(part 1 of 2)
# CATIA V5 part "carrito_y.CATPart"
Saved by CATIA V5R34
Part number: Part4
Bounding box of the stored display mesh (mm): x -115.5 to 115.5, y -20 to 5, z -75 to 75
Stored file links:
  C:\Users\Apolinar\Desktop\cnc\carrito_y.CATPart
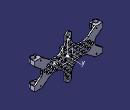
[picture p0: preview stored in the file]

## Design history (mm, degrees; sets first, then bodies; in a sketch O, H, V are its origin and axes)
AxisSystem1: origin (0, 0, 0), X (1, 0, 0), Y (0, 1, 0), Z (0, 0, 1)
Body1 (main body)
  Sketch1 on ZX plane of AxisSystem1, origin (0, 0, 0), H (0, 0, 1), V (1, 0, 0)
    point P1 (-20, 58.9576)
    point P2 (-45, 116.5)
    line L1 (-45, 116.5) -> (-30, 116.5)
    point P3 (-30, 116.5)
    line L2 (-30, 116.5) -> (-9.642, 90)
    point P4 (-9.642, 90)
    line L3 (-9.642, 90) -> (0, 90)
    point P5 (0, 90)
    line L4 (-20, 58.9576) -> (-20, 31.2132)
    point P6 (-20, 0)
    point P7 (0, 90)
    point P8 (-20, 0)
    line L5 (-45, 116.5) -> (-45, 91.5)
    point P9 (-45, 91.5)
    line L6 (-45, 91.5) -> (-20, 58.9576)
    point P10 (20, 58.9576)
    point P11 (45, 116.5)
    point P12 (30, 116.5)
    point P13 (9.642, 90)
    point P14 (20, 0)
    point P15 (45, 91.5)
    line L7 (45, 116.5) -> (30, 116.5)
    line L8 (30, 116.5) -> (9.642, 90)
    line L9 (20, 58.9576) -> (20, 31.2132)
    line L10 (45, 116.5) -> (45, 91.5)
    line L11 (45, 91.5) -> (20, 58.9576)
    point P16 (0, 90)
    line L12 (9.642, 90) -> (0, 90)
    point P17 (-45, -116.5)
    point P18 (-30, -116.5)
    point P19 (-9.642, -90)
    point P20 (0, -90)
    point P21 (0, -90)
    point P22 (-45, -91.5)
    point P23 (45, -116.5)
    point P24 (30, -116.5)
    point P25 (9.642, -90)
    point P26 (45, -91.5)
    point P27 (0, -90)
    line L13 (-45, -116.5) -> (-30, -116.5)
    line L14 (-30, -116.5) -> (-9.642, -90)
    line L15 (-9.642, -90) -> (0, -90)
    line L16 (-45, -116.5) -> (-45, -91.5)
    line L17 (45, -116.5) -> (30, -116.5)
    line L18 (30, -116.5) -> (9.642, -90)
    line L19 (45, -116.5) -> (45, -91.5)
    line L20 (9.642, -90) -> (0, -90)
    point P28 (20, -58.9576)
    line L21 (45, -91.5) -> (20, -58.9576)
    point P29 (20, 0)
    line L22 (20, -58.9576) -> (20, -31.2132)
    point P30 (-20, -58.9576)
    point P31 (-20, 0)
    line L23 (-20, -58.9576) -> (-20, -31.2132)
    line L24 (-45, -91.5) -> (-20, -58.9576)
    construction line L25 (-45, 104) -> (-65.3473, 104)
    point P32 (-45, 104)
    axis line L26 (-45, -104) -> (-57.4598, -104)
    point P34 (-45, -104)
    point P36 (-20, 10)
    line L27 (-41.2132, 10) -> (-69.2265, 10)
    point P37 (-69.2265, 10)
    line L28 (-69.2265, 10) -> (-75, 0)
    point P38 (-75, 0)
    point P39 (-75, 0)
    point P40 (-69.2265, -10)
    line L29 (-69.2265, -10) -> (-75, 0)
    point P41 (-20, -10)
    line L30 (-41.2132, -10) -> (-69.2265, -10)
    point P42 (69.2265, 10)
    point P43 (75, 0)
    point P44 (75, 0)
    point P45 (69.2265, -10)
    line L31 (69.2265, 10) -> (75, 0)
    line L32 (69.2265, -10) -> (75, 0)
    point P46 (20, 10)
    line L33 (41.2132, 10) -> (69.2265, 10)
    point P47 (20, -10)
    line L34 (41.2132, -10) -> (69.2265, -10)
    line L35 (-41.2132, 10) -> (-20, 31.2132)
    line L36 (41.2132, 10) -> (20, 31.2132)
    line L37 (41.2132, -10) -> (20, -31.2132)
    line L38 (-41.2132, -10) -> (-20, -31.2132)
    length L1 = 15
    length L5 = 25
    distance L25 L26 = 208
    distance P3 P12 = 60
    distance L4 V = 20
    distance L3 H = 90
    length L6 = 41.0367
    distance P38 L4 = 55
    distance L30 L27 = 20
    angle L27 L35 = 45
    length L35 = 30
    angle L33 L36 = 45
    length L36 = 30
    angle L34 L37 = 45
    length L37 = 30
    angle L30 L38 = 45
    length L38 = 30
    angle L29 L30 = 120
    horizontal: L1 H, L3 H, L25 H, L26 H, L27 H
    coincidence: P5 V, P6 H, P5 P7, P6 P8, P4 L12, P38 H, L27 P36, L4 P36, L33 P46, L9 P46, L34 P47, L22 P47, L30 P41, L23 P41
    vertical: L4 V, L5 V
    parallelism: L6 L2
    symmetry: P1 P10 V, P2 P11 V, P3 P12 V, P4 P13 V, P8 P14 V, P9 P15 V, L1 L7 V, L2 L8 V, L4 L9 V, L5 L10 V, L6 L11 V, P5 P16 V, L3 L12 V, P2 P17 H, P3 P18 H, P4 P19 H, P5 P20 H, P7 P21 H, P9 P22 H, P11 P23 H, P12 P24 H, P13 P25 H, P15 P26 H, P16 P27 H, L1 L13 H, L2 L14 H, L3 L15 H, L5 L16 H, L7 L17 H, L8 L18 H, L10 L19 H, L12 L20 H, P10 P28 H, L11 L21 H, P14 P29 H, L9 L22 H, P1 P30 H, P8 P31 H, L4 L23 H, L6 L24 H, P38 P39 H, P37 P40 H, L28 L29 H, P36 P41 H, L27 L30 H, P37 P42 V, P38 P43 V, P39 P44 V, P40 P45 V, L28 L31 V, L29 L32 V, P36 P46 V, L27 L33 V, P41 P47 V, L30 L34 V
    midpoint: P34 L16, L5 P32
  Pad1: profile Sketch1, direction (0, 1, 0), length 5
  Sketch2 on start face of Pad1, origin (0, 0, 0), H (1, 0, 0), V (0, 0, 1)
    point P1 (-116.5, 45)
    line L1 (-116.5, 45) -> (-91.5, 45)
    line L2 (-91.5, 45) -> (-91.5, 30)
    line L3 (-91.5, 30) -> (-116.5, 30)
    line L4 (-116.5, 30) -> (-116.5, 45)
    point P2 (-91.5, 45)
    point P3 (-91.5, 30)
    point P4 (-116.5, 30)
    reference projected line E1 (-116.5, 30) -> (-116.5, 45) from edge [start face of Pad1 | face of Pad1 from Sketch1.L17]
    reference projected point E2 (-116.5, 30) from vertex [start face of Pad1 | face of Pad1 from Sketch1.L18 | face of Pad1 from Sketch1.L17]
    point P5 (116.5, 45)
    point P6 (91.5, 45)
    point P7 (91.5, 30)
    point P8 (116.5, 30)
    line L5 (116.5, 45) -> (91.5, 45)
    line L6 (91.5, 45) -> (91.5, 30)
    line L7 (91.5, 30) -> (116.5, 30)
    line L8 (116.5, 30) -> (116.5, 45)
    point P9 (-116.5, -45)
    point P10 (-91.5, -45)
    point P11 (-91.5, -30)
    point P12 (-116.5, -30)
    point P13 (116.5, -45)
    point P14 (91.5, -45)
    point P15 (91.5, -30)
    point P16 (116.5, -30)
    line L9 (-116.5, -45) -> (-91.5, -45)
    line L10 (-91.5, -45) -> (-91.5, -30)
    line L11 (-91.5, -30) -> (-116.5, -30)
    line L12 (-116.5, -30) -> (-116.5, -45)
    line L13 (116.5, -45) -> (91.5, -45)
    line L14 (91.5, -45) -> (91.5, -30)
    line L15 (91.5, -30) -> (116.5, -30)
    line L16 (116.5, -30) -> (116.5, -45)
    reference projected point E3 (-91.5, 45) from vertex [start face of Pad1 | face of Pad1 from Sketch1.L19 | face of Pad1 from Sketch1.L21]
    length L4 = 15
    horizontal: L1 H, L3 H
    vertical: L2 V, L4 V
    coincidence: E1 L4, E2 L3, L2 E3
    symmetry: P1 P5 V, P2 P6 V, P3 P7 V, P4 P8 V, L1 L5 V, L2 L6 V, L3 L7 V, L4 L8 V, P1 P9 H, P2 P10 H, P3 P11 H, P4 P12 H, P5 P13 H, P6 P14 H, P7 P15 H, P8 P16 H, L1 L9 H, L2 L10 H, L3 L11 H, L4 L12 H, L5 L13 H, L6 L14 H, L7 L15 H, L8 L16 H
  Pad2: profile Sketch2, direction (0, -1, 0), length 20
  Sketch3 on face of Pad2, origin (0, 0, -45), H (1, 0, 0), V (0, -1, 0)
    arc A1 centre (-107, 10) radius 7.5 from (-99.567, 11) to (-99.567, 9) ccw
    point P1 (-107, 10)
    point P2 (-99.567, 11)
    line L1 (-99.567, 11) -> (-91.5, 11)
    point P3 (-91.5, 11)
    line L2 (-91.5, 11) -> (-91.5, 9)
    point P4 (-91.5, 9)
    line L3 (-91.5, 9) -> (-99.567, 9)
    point P5 (-99.567, 9)
    reference projected line E1 (-116.5, 0) -> (-116.5, -5) from edge [face of Pad2 | face of Pad2]
    reference projected line E2 (-58.9576, 0) -> (-91.5, 0) from edge [start face of Pad1 | face of Pad1 from Sketch1.L24]
    reference projected line E3 (-91.5, 0) -> (-91.5, 20) from edge [face of Pad2 from Sketch2.L10 | face of Pad2]
    point P7 (99.567, 11)
    point P8 (91.5, 11)
    point P9 (91.5, 9)
    point P10 (99.567, 9)
    arc A2 centre (107, 10) radius 7.5 from (99.567, 11) to (99.567, 9) cw
    line L4 (99.567, 11) -> (91.5, 11)
    line L5 (91.5, 11) -> (91.5, 9)
    line L6 (91.5, 9) -> (99.567, 9)
    radius A1 = 7.5
    length L2 = 2
    distance E1 A1 = 2
    distance E2 P1 = 10
    distance P3 P1 V = 1
    horizontal: L1 H, L3 H
    vertical: L2 V
    coincidence: L2 E3
    symmetry: P2 P7 V, P3 P8 V, P4 P9 V, P5 P10 V, A1 A2 V, L1 L4 V, L2 L5 V, L3 L6 V
  Pocket1: profile Sketch3, direction (0, 0, 1), through (limit type 3)
  Sketch4 on start face of Pad1, origin (0, 0, 0), H (1, 0, 0), V (0, 0, 1)
    point P1 (0, 5)
    construction circle A1 centre (0, 0) radius 5.7735
    construction circle A2 centre (0, 0) radius 5
    point P2 (2.8868, 5)
    point P3 (-2.8868, 5)
    point P4 (-5.7735, 0)
    point P5 (-2.8868, -5)
    point P6 (2.8868, -5)
    point P7 (5.7735, 0)
    line L1 (2.8868, 5) -> (-2.8868, 5)
    line L2 (-2.8868, 5) -> (-5.7735, 0)
    line L3 (-5.7735, 0) -> (-2.8868, -5)
    line L4 (-2.8868, -5) -> (2.8868, -5)
    line L5 (2.8868, -5) -> (5.7735, 0)
    line L6 (5.7735, 0) -> (2.8868, 5)
    construction line L7 (0, 0) -> (0, 5)
    point P8 (-20, 5)
    point P9 (-17.1132, 5)
    point P10 (-22.8868, 5)
    line L8 (-17.1132, 5) -> (-22.8868, 5)
    point P11 (-17.1132, -5)
    point P12 (-22.8868, -5)
    line L9 (-22.8868, -5) -> (-17.1132, -5)
    point P13 (-14.2265, 0)
    line L10 (-17.1132, -5) -> (-14.2265, 0)
    line L11 (-14.2265, 0) -> (-17.1132, 5)
    point P14 (-25.7735, 0)
    line L12 (-22.8868, 5) -> (-25.7735, 0)
    line L13 (-25.7735, 0) -> (-22.8868, -5)
    point P15 (-40, 5)
    point P16 (-37.1132, 5)
    point P17 (-42.8868, 5)
    line L14 (-37.1132, 5) -> (-42.8868, 5)
    point P18 (-37.1132, -5)
    point P19 (-42.8868, -5)
    line L15 (-42.8868, -5) -> (-37.1132, -5)
    point P20 (-34.2265, 0)
    line L16 (-37.1132, -5) -> (-34.2265, 0)
    line L17 (-34.2265, 0) -> (-37.1132, 5)
    point P21 (-45.7735, 0)
    line L18 (-42.8868, 5) -> (-45.7735, 0)
    line L19 (-45.7735, 0) -> (-42.8868, -5)
    point P22 (-60, 5)
    point P23 (-57.1132, 5)
    point P24 (-62.8868, 5)
    line L20 (-57.1132, 5) -> (-62.8868, 5)
    point P25 (-57.1132, -5)
    point P26 (-62.8868, -5)
    line L21 (-62.8868, -5) -> (-57.1132, -5)
    point P27 (-54.2265, 0)
    line L22 (-57.1132, -5) -> (-54.2265, 0)
    line L23 (-54.2265, 0) -> (-57.1132, 5)
    point P28 (-65.7735, 0)
    line L24 (-62.8868, 5) -> (-65.7735, 0)
    line L25 (-65.7735, 0) -> (-62.8868, -5)
    point P29 (-80, 5)
    point P30 (-77.1132, 5)
    point P31 (-82.8868, 5)
    line L26 (-77.1132, 5) -> (-82.8868, 5)
    point P32 (-77.1132, -5)
    point P33 (-82.8868, -5)
    line L27 (-82.8868, -5) -> (-77.1132, -5)
    point P34 (-74.2265, 0)
    line L28 (-77.1132, -5) -> (-74.2265, 0)
    line L29 (-74.2265, 0) -> (-77.1132, 5)
    point P35 (-85.7735, 0)
    line L30 (-82.8868, 5) -> (-85.7735, 0)
    line L31 (-85.7735, 0) -> (-82.8868, -5)
    point P36 (20, 5)
    point P37 (17.1132, 5)
    point P38 (22.8868, 5)
    point P39 (17.1132, -5)
    point P40 (22.8868, -5)
    point P41 (14.2265, 0)
    point P42 (25.7735, 0)
    point P43 (40, 5)
    point P44 (37.1132, 5)
    point P45 (42.8868, 5)
    point P46 (37.1132, -5)
    point P47 (42.8868, -5)
    point P48 (34.2265, 0)
    point P49 (45.7735, 0)
    point P50 (60, 5)
    point P51 (57.1132, 5)
    point P52 (62.8868, 5)
    point P53 (57.1132, -5)
    point P54 (62.8868, -5)
    point P55 (54.2265, 0)
    point P56 (65.7735, 0)
    point P57 (80, 5)
    point P58 (77.1132, 5)
    point P59 (82.8868, 5)
    point P60 (77.1132, -5)
    point P61 (82.8868, -5)
    point P62 (74.2265, 0)
    point P63 (85.7735, 0)
    line L32 (17.1132, 5) -> (22.8868, 5)
    line L33 (22.8868, -5) -> (17.1132, -5)
    line L34 (17.1132, -5) -> (14.2265, 0)
    line L35 (14.2265, 0) -> (17.1132, 5)
    line L36 (22.8868, 5) -> (25.7735, 0)
    line L37 (25.7735, 0) -> (22.8868, -5)
    line L38 (37.1132, 5) -> (42.8868, 5)
    line L39 (42.8868, -5) -> (37.1132, -5)
    line L40 (37.1132, -5) -> (34.2265, 0)
    line L41 (34.2265, 0) -> (37.1132, 5)
    line L42 (42.8868, 5) -> (45.7735, 0)
    line L43 (45.7735, 0) -> (42.8868, -5)
    line L44 (57.1132, 5) -> (62.8868, 5)
    line L45 (62.8868, -5) -> (57.1132, -5)
    line L46 (57.1132, -5) -> (54.2265, 0)
    line L47 (54.2265, 0) -> (57.1132, 5)
    line L48 (62.8868, 5) -> (65.7735, 0)
    line L49 (65.7735, 0) -> (62.8868, -5)
    line L50 (77.1132, 5) -> (82.8868, 5)
    line L51 (82.8868, -5) -> (77.1132, -5)
    line L52 (77.1132, -5) -> (74.2265, 0)
    line L53 (74.2265, 0) -> (77.1132, 5)
    line L54 (82.8868, 5) -> (85.7735, 0)
    line L55 (85.7735, 0) -> (82.8868, -5)
    point P64 (9.9998, 10)
    point P65 (9.9998, 15)
    construction circle A3 centre (9.9998, 10) radius 5.7735
    construction circle A4 centre (9.9998, 10) radius 5
    point P66 (12.8865, 15)
    point P67 (7.113, 15)
    point P68 (4.2262, 10)
    point P69 (7.113, 5)
    point P70 (12.8865, 5)
    point P71 (15.7733, 10)
    line L56 (12.8865, 15) -> (7.113, 15)
    line L57 (7.113, 15) -> (4.2262, 10)
    line L58 (4.2262, 10) -> (7.113, 5)
    line L59 (7.113, 5) -> (12.8865, 5)
    line L60 (12.8865, 5) -> (15.7733, 10)
    line L61 (15.7733, 10) -> (12.8865, 15)
    construction line L62 (9.9998, 10) -> (9.9998, 15)
    axis line L63 (9.9998, 3.7561) -> (9.9998, 5)
    point P72 (9.9998, 3.7561)
    point P73 (9.9998, 5)
    point P74 (29.9998, 10)
    point P75 (29.9998, 15)
    construction circle A5 centre (29.9998, 10) radius 5.7735
    construction circle A6 centre (29.9998, 10) radius 5
    point P76 (32.8865, 15)
    point P77 (27.113, 15)
    point P78 (24.2262, 10)
    point P79 (27.113, 5)
    point P80 (32.8865, 5)
    point P81 (35.7733, 10)
    construction line L64 (29.9998, 10) -> (29.9998, 15)
    point P82 (29.9998, 3.7561)
    point P83 (29.9998, 5)
    construction line L65 (29.9998, 3.7561) -> (29.9998, 5)
    line L66 (32.8865, 15) -> (27.113, 15)
    line L67 (27.113, 15) -> (24.2262, 10)
    line L68 (24.2262, 10) -> (27.113, 5)
    line L69 (27.113, 5) -> (32.8865, 5)
    line L70 (32.8865, 5) -> (35.7733, 10)
    line L71 (35.7733, 10) -> (32.8865, 15)
    point P84 (49.9998, 10)
    point P85 (49.9998, 15)
    construction circle A7 centre (49.9998, 10) radius 5.7735
    construction circle A8 centre (49.9998, 10) radius 5
    point P86 (52.8865, 15)
    point P87 (47.113, 15)
    point P88 (44.2262, 10)
    point P89 (47.113, 5)
    point P90 (52.8865, 5)
    point P91 (55.7733, 10)
    construction line L72 (49.9998, 10) -> (49.9998, 15)
    point P92 (49.9998, 3.7561)
    point P93 (49.9998, 5)
    construction line L73 (49.9998, 3.7561) -> (49.9998, 5)
    line L74 (52.8865, 15) -> (47.113, 15)
    line L75 (47.113, 15) -> (44.2262, 10)
    line L76 (44.2262, 10) -> (47.113, 5)
    line L77 (47.113, 5) -> (52.8865, 5)
    line L78 (52.8865, 5) -> (55.7733, 10)
    line L79 (55.7733, 10) -> (52.8865, 15)
    point P94 (69.9998, 10)
    point P95 (69.9998, 15)
    construction circle A9 centre (69.9998, 10) radius 5.7735
    construction circle A10 centre (69.9998, 10) radius 5
    point P96 (72.8865, 15)
    point P97 (67.113, 15)
    point P98 (64.2262, 10)
    point P99 (67.113, 5)
    point P100 (72.8865, 5)
    point P101 (75.7733, 10)
    construction line L80 (69.9998, 10) -> (69.9998, 15)
    point P102 (69.9998, 3.7561)
    point P103 (69.9998, 5)
    construction line L81 (69.9998, 3.7561) -> (69.9998, 5)
    line L82 (72.8865, 15) -> (67.113, 15)
    line L83 (67.113, 15) -> (64.2262, 10)
    line L84 (64.2262, 10) -> (67.113, 5)
    line L85 (67.113, 5) -> (72.8865, 5)
    line L86 (72.8865, 5) -> (75.7733, 10)
    line L87 (75.7733, 10) -> (72.8865, 15)
    point P104 (-29.9998, 10)
    point P105 (-29.9998, 15)
    construction circle A11 centre (-29.9998, 10) radius 5.7735
    construction circle A12 centre (-29.9998, 10) radius 5
    point P106 (-32.8865, 15)
    point P107 (-27.113, 15)
    point P108 (-24.2262, 10)
    point P109 (-27.113, 5)
    point P110 (-32.8865, 5)
    point P111 (-35.7733, 10)
    construction line L88 (-29.9998, 10) -> (-29.9998, 15)
    point P112 (-29.9998, 3.7561)
    point P113 (-29.9998, 5)
    construction line L89 (-29.9998, 3.7561) -> (-29.9998, 5)
    line L90 (-32.8865, 15) -> (-27.113, 15)
    line L91 (-27.113, 15) -> (-24.2262, 10)
    line L92 (-24.2262, 10) -> (-27.113, 5)
    line L93 (-27.113, 5) -> (-32.8865, 5)
    line L94 (-32.8865, 5) -> (-35.7733, 10)
    line L95 (-35.7733, 10) -> (-32.8865, 15)
    point P114 (-49.9998, 10)
    point P115 (-49.9998, 15)
    construction circle A13 centre (-49.9998, 10) radius 5.7735
    construction circle A14 centre (-49.9998, 10) radius 5
    point P116 (-52.8865, 15)
    point P117 (-47.113, 15)
    point P118 (-44.2262, 10)
    point P119 (-47.113, 5)
    point P120 (-52.8865, 5)
    point P121 (-55.7733, 10)
    construction line L96 (-49.9998, 10) -> (-49.9998, 15)
    point P122 (-49.9998, 3.7561)
    point P123 (-49.9998, 5)
    construction line L97 (-49.9998, 3.7561) -> (-49.9998, 5)
    line L98 (-52.8865, 15) -> (-47.113, 15)
    line L99 (-47.113, 15) -> (-44.2262, 10)
    line L100 (-44.2262, 10) -> (-47.113, 5)
    line L101 (-47.113, 5) -> (-52.8865, 5)
    line L102 (-52.8865, 5) -> (-55.7733, 10)
    line L103 (-55.7733, 10) -> (-52.8865, 15)
    point P124 (-69.9998, 10)
    point P125 (-69.9998, 15)
    construction circle A15 centre (-69.9998, 10) radius 5.7735
    construction circle A16 centre (-69.9998, 10) radius 5
    point P126 (-72.8865, 15)
    point P127 (-67.113, 15)
    point P128 (-64.2262, 10)
    point P129 (-67.113, 5)
    point P130 (-72.8865, 5)
    point P131 (-75.7733, 10)
    construction line L104 (-69.9998, 10) -> (-69.9998, 15)
    point P132 (-69.9998, 3.7561)
    point P133 (-69.9998, 5)
    construction line L105 (-69.9998, 3.7561) -> (-69.9998, 5)
    line L106 (-72.8865, 15) -> (-67.113, 15)
    line L107 (-67.113, 15) -> (-64.2262, 10)
    line L108 (-64.2262, 10) -> (-67.113, 5)
    line L109 (-67.113, 5) -> (-72.8865, 5)
    line L110 (-72.8865, 5) -> (-75.7733, 10)
    line L111 (-75.7733, 10) -> (-72.8865, 15)
    point P134 (-9.9998, 10)
    point P135 (-9.9998, 15)
    construction circle A17 centre (-9.9998, 10) radius 5
    point P136 (-12.8865, 15)
    point P137 (-7.113, 15)
    point P138 (-7.113, 5)
    point P139 (-12.8865, 5)
    point P140 (-15.7733, 10)
    construction line L112 (-9.9998, 10) -> (-9.9998, 15)
    point P141 (-9.9998, 5)
    point P142 (-9.9998, 3.7561)
    construction line L113 (-9.9998, 3.7561) -> (-9.9998, 5)
    line L114 (-12.8865, 15) -> (-7.113, 15)
    line L115 (-7.113, 5) -> (-12.8865, 5)
    line L116 (-12.8865, 5) -> (-15.7733, 10)
    line L117 (-15.7733, 10) -> (-12.8865, 15)
    point P143 (-4.2262, 10)
    line L118 (-7.113, 15) -> (-4.2262, 10)
    line L119 (-4.2262, 10) -> (-7.113, 5)
    point P144 (9.9998, -10)
    point P145 (9.9998, -15)
    point P146 (12.8865, -15)
    point P147 (7.113, -15)
    point P148 (4.2262, -10)
    point P149 (15.7733, -10)
    construction line L120 (9.9998, -10) -> (9.9998, -15)
    point P150 (29.9998, -10)
    point P151 (29.9998, -15)
    point P152 (32.8865, -15)
    point P153 (27.113, -15)
    point P154 (24.2262, -10)
    point P155 (35.7733, -10)
    construction line L121 (29.9998, -10) -> (29.9998, -15)
    point P156 (49.9998, -10)
    point P157 (49.9998, -15)
    point P158 (52.8865, -15)
    point P159 (47.113, -15)
    point P160 (44.2262, -10)
    point P161 (55.7733, -10)
    construction line L122 (49.9998, -10) -> (49.9998, -15)
    point P162 (69.9998, -10)
    point P163 (69.9998, -15)
    point P164 (72.8865, -15)
    point P165 (67.113, -15)
    point P166 (64.2262, -10)
    point P167 (75.7733, -10)
    construction line L123 (69.9998, -10) -> (69.9998, -15)
    point P168 (-29.9998, -10)
    point P169 (-29.9998, -15)
    point P170 (-32.8865, -15)
    point P171 (-27.113, -15)
    point P172 (-24.2262, -10)
    point P173 (-35.7733, -10)
    construction line L124 (-29.9998, -10) -> (-29.9998, -15)
    point P174 (-49.9998, -10)
    point P175 (-49.9998, -15)
    point P176 (-52.8865, -15)
    point P177 (-47.113, -15)
    point P178 (-44.2262, -10)
    point P179 (-55.7733, -10)
    construction line L125 (-49.9998, -10) -> (-49.9998, -15)
    point P180 (-69.9998, -10)
    point P181 (-69.9998, -15)
    point P182 (-72.8865, -15)
    point P183 (-67.113, -15)
    point P184 (-64.2262, -10)
    point P185 (-75.7733, -10)
    construction line L126 (-69.9998, -10) -> (-69.9998, -15)
    point P186 (-9.9998, -10)
    point P187 (-9.9998, -15)
    point P188 (-12.8865, -15)
    point P189 (-7.113, -15)
    point P190 (-15.7733, -10)
    construction line L127 (-9.9998, -10) -> (-9.9998, -15)
    point P191 (-4.2262, -10)
    line L128 (12.8865, -15) -> (7.113, -15)
    line L129 (7.113, -15) -> (4.2262, -10)
    line L130 (15.7733, -10) -> (12.8865, -15)
    line L131 (32.8865, -15) -> (27.113, -15)
    line L132 (27.113, -15) -> (24.2262, -10)
    line L133 (35.7733, -10) -> (32.8865, -15)
    line L134 (52.8865, -15) -> (47.113, -15)
    line L135 (47.113, -15) -> (44.2262, -10)
    line L136 (55.7733, -10) -> (52.8865, -15)
    line L137 (72.8865, -15) -> (67.113, -15)
    line L138 (67.113, -15) -> (64.2262, -10)
    line L139 (75.7733, -10) -> (72.8865, -15)
    line L140 (-32.8865, -15) -> (-27.113, -15)
    line L141 (-27.113, -15) -> (-24.2262, -10)
    line L142 (-35.7733, -10) -> (-32.8865, -15)
    line L143 (-52.8865, -15) -> (-47.113, -15)
    line L144 (-47.113, -15) -> (-44.2262, -10)
    line L145 (-55.7733, -10) -> (-52.8865, -15)
    line L146 (-72.8865, -15) -> (-67.113, -15)
    line L147 (-67.113, -15) -> (-64.2262, -10)
    line L148 (-75.7733, -10) -> (-72.8865, -15)
    line L149 (-12.8865, -15) -> (-7.113, -15)
    line L150 (-15.7733, -10) -> (-12.8865, -15)
    line L151 (-7.113, -15) -> (-4.2262, -10)
    point P192 (-72.8865, -5)
    point P193 (-67.113, -5)
    line L152 (-67.113, -5) -> (-72.8865, -5)
    line L153 (-72.8865, -5) -> (-75.7733, -10)
    line L154 (-64.2262, -10) -> (-67.113, -5)
    point P194 (-52.8865, -5)
    line L155 (-52.8865, -5) -> (-55.7733, -10)
    point P195 (-47.113, -5)
    line L156 (-47.113, -5) -> (-52.8865, -5)
    line L157 (-44.2262, -10) -> (-47.113, -5)
    point P196 (-32.8865, -5)
    line L158 (-32.8865, -5) -> (-35.7733, -10)
    point P197 (-27.113, -5)
    line L159 (-27.113, -5) -> (-32.8865, -5)
    line L160 (-24.2262, -10) -> (-27.113, -5)
    point P198 (-12.8865, -5)
    line L161 (-12.8865, -5) -> (-15.7733, -10)
    point P199 (-7.113, -5)
    line L162 (-7.113, -5) -> (-12.8865, -5)
    line L163 (-4.2262, -10) -> (-7.113, -5)
    point P200 (7.113, -5)
    line L164 (4.2262, -10) -> (7.113, -5)
    point P201 (12.8865, -5)
    line L165 (7.113, -5) -> (12.8865, -5)
    line L166 (12.8865, -5) -> (15.7733, -10)
    point P202 (27.113, -5)
    line L167 (24.2262, -10) -> (27.113, -5)
    point P203 (32.8865, -5)
    line L168 (27.113, -5) -> (32.8865, -5)
    line L169 (32.8865, -5) -> (35.7733, -10)
    point P204 (47.113, -5)
    line L170 (44.2262, -10) -> (47.113, -5)
    point P205 (52.8865, -5)
    line L171 (47.113, -5) -> (52.8865, -5)
    line L172 (52.8865, -5) -> (55.7733, -10)
    point P206 (67.113, -5)
    line L173 (64.2262, -10) -> (67.113, -5)
    point P207 (72.8865, -5)
    line L174 (67.113, -5) -> (72.8865, -5)
    line L175 (72.8865, -5) -> (75.7733, -10)
    point P208 (-2.8868, -25)
    point P209 (-5.7735, -20)
    line L176 (-5.7735, -20) -> (-2.8868, -25)
    point P210 (-2.8868, -15)
    line L177 (-2.8868, -15) -> (-5.7735, -20)
    point P211 (2.8868, -15)
    line L178 (2.8868, -15) -> (-2.8868, -15)
    point P212 (5.7735, -20)
    line L179 (5.7735, -20) -> (2.8868, -15)
    point P213 (2.8868, -25)
    line L180 (2.8868, -25) -> (5.7735, -20)
    line L181 (-2.8868, -25) -> (2.8868, -25)
    point P214 (-14.2265, -20)
    point P215 (-17.1132, -25)
    line L182 (-17.1132, -25) -> (-14.2265, -20)
    point P216 (-17.1132, -15)
    line L183 (-14.2265, -20) -> (-17.1132, -15)
    point P217 (-22.8868, -15)
    line L184 (-17.1132, -15) -> (-22.8868, -15)
    point P218 (-25.7735, -20)
    line L185 (-22.8868, -15) -> (-25.7735, -20)
    point P219 (-22.8868, -25)
    line L186 (-25.7735, -20) -> (-22.8868, -25)
    line L187 (-22.8868, -25) -> (-17.1132, -25)
    point P220 (17.1132, -15)
    point P221 (14.2265, -20)
    line L188 (14.2265, -20) -> (17.1132, -15)
    point P222 (17.1132, -25)
    line L189 (17.1132, -25) -> (14.2265, -20)
    point P223 (25.7735, -20)
    point P224 (22.8868, -15)
    line L190 (22.8868, -15) -> (25.7735, -20)
    line L191 (17.1132, -15) -> (22.8868, -15)
    point P225 (22.8868, -25)
    line L192 (22.8868, -25) -> (17.1132, -25)
    line L193 (25.7735, -20) -> (22.8868, -25)
    point P226 (7.113, -35)
    point P227 (12.8865, -35)
    line L194 (12.8865, -35) -> (7.113, -35)
    point P228 (4.2262, -30)
    line L195 (7.113, -35) -> (4.2262, -30)
    point P229 (7.113, -25)
    line L196 (4.2262, -30) -> (7.113, -25)
    point P230 (12.8865, -25)
    line L197 (7.113, -25) -> (12.8865, -25)
    point P231 (15.7733, -30)
    line L198 (12.8865, -25) -> (15.7733, -30)
    line L199 (15.7733, -30) -> (12.8865, -35)
    point P232 (-4.2262, -30)
    point P233 (-7.113, -35)
    line L200 (-7.113, -35) -> (-4.2262, -30)
    point P234 (-7.113, -25)
    line L201 (-4.2262, -30) -> (-7.113, -25)
    point P235 (-12.8865, -25)
    line L202 (-7.113, -25) -> (-12.8865, -25)
    point P236 (-15.7733, -30)
    line L203 (-12.8865, -25) -> (-15.7733, -30)
    point P237 (-12.8865, -35)
    line L204 (-15.7733, -30) -> (-12.8865, -35)
    line L205 (-12.8865, -35) -> (-7.113, -35)
    point P238 (2.8868, -65)
    point P239 (-2.8868, -65)
    line L206 (-2.8868, -65) -> (2.8868, -65)
    point P240 (-5.7735, -60)
    line L207 (-5.7735, -60) -> (-2.8868, -65)
    point P241 (-2.8868, -55)
    line L208 (-2.8868, -55) -> (-5.7735, -60)
    point P242 (2.8868, -55)
    line L209 (2.8868, -55) -> (-2.8868, -55)
    point P243 (5.7735, -60)
    line L210 (5.7735, -60) -> (2.8868, -55)
    line L211 (2.8868, -65) -> (5.7735, -60)
    point P244 (-2.8868, -45)
    point P245 (-5.7735, -40)
    line L212 (-5.7735, -40) -> (-2.8868, -45)
    point P246 (-2.8868, -35)
    line L213 (-2.8868, -35) -> (-5.7735, -40)
    point P247 (2.8868, -35)
    line L214 (2.8868, -35) -> (-2.8868, -35)
    point P248 (5.7735, -40)
    line L215 (5.7735, -40) -> (2.8868, -35)
    point P249 (2.8868, -45)
    line L216 (2.8868, -45) -> (5.7735, -40)
    line L217 (-2.8868, -45) -> (2.8868, -45)
    point P250 (0, -20)
    construction line L218 (0, -20) -> (0, -15)
    point P252 (-20, -15)
    point P253 (-40, -15)
    point P254 (-37.1132, -15)
    point P255 (-42.8868, -15)
    point P256 (-60, -15)
    point P257 (-57.1132, -15)
    point P258 (-62.8868, -15)
    point P259 (20, -15)
    point P260 (40, -15)
    point P261 (37.1132, -15)
    point P262 (42.8868, -15)
    point P263 (60, -15)
    point P264 (57.1132, -15)
    point P265 (62.8868, -15)
    line L219 (-37.1132, -15) -> (-42.8868, -15)
    line L220 (-35.9585, -17) -> (-37.1132, -15)
    line L221 (-42.8868, -15) -> (-44.0415, -17)
    line L222 (-57.1132, -15) -> (-62.8868, -15)
    line L223 (-55.9585, -17) -> (-57.1132, -15)
    line L224 (-62.8868, -15) -> (-64.0415, -17)
    line L225 (37.1132, -15) -> (42.8868, -15)
    line L226 (35.9585, -17) -> (37.1132, -15)
    line L227 (42.8868, -15) -> (44.0415, -17)
    line L228 (57.1132, -15) -> (62.8868, -15)
    line L229 (55.9585, -17) -> (57.1132, -15)
    line L230 (62.8868, -15) -> (64.0415, -17)
    line L231 (64.0415, -17) -> (55.9585, -17)
    point P266 (64.0415, -17)
    point P267 (55.9585, -17)
    line L232 (44.0415, -17) -> (35.9585, -17)
    point P268 (44.0415, -17)
    point P269 (35.9585, -17)
    line L233 (-35.9585, -17) -> (-44.0415, -17)
    point P270 (-35.9585, -17)
    point P271 (-44.0415, -17)
    point P272 (-55.9585, -17)
    line L234 (-55.9585, -17) -> (-64.0415, -17)
    point P273 (-64.0415, -17)
    point P274 (7.113, -55)
    point P275 (4.2262, -50)
    line L235 (4.2262, -50) -> (7, -54.8043)
    point P276 (7.113, -45)
    line L236 (7, -45.1957) -> (4.2262, -50)
    point P277 (7, -45.1957)
    line L237 (7, -54.8043) -> (7, -45.1957)
    point P278 (7, -54.8043)
    point P279 (-7.113, -55)
    point P280 (-4.2262, -50)
    point P281 (-7.113, -45)
    point P282 (-7, -45.1957)
    point P283 (-7, -54.8043)
    line L238 (-4.2262, -50) -> (-7, -54.8043)
    line L239 (-7, -45.1957) -> (-4.2262, -50)
    line L240 (-7, -54.8043) -> (-7, -45.1957)
    point P284 (-40, 15)
    point P285 (-37.1132, 15)
    point P286 (-42.8868, 15)
    point P287 (-35.9585, 17)
    point P288 (-44.0415, 17)
    line L241 (-37.1132, 15) -> (-42.8868, 15)
    line L242 (-35.9585, 17) -> (-37.1132, 15)
    line L243 (-42.8868, 15) -> (-44.0415, 17)
    line L244 (-35.9585, 17) -> (-44.0415, 17)
    point P289 (-60, 15)
    point P290 (-57.1132, 15)
    point P291 (-62.8868, 15)
    point P292 (-55.9585, 17)
    point P293 (-64.0415, 17)
    line L245 (-57.1132, 15) -> (-62.8868, 15)
    line L246 (-55.9585, 17) -> (-57.1132, 15)
    line L247 (-62.8868, 15) -> (-64.0415, 17)
    line L248 (-55.9585, 17) -> (-64.0415, 17)
    point P294 (40, 15)
    point P295 (37.1132, 15)
    point P296 (42.8868, 15)
    point P297 (44.0415, 17)
    point P298 (35.9585, 17)
    line L249 (37.1132, 15) -> (42.8868, 15)
    line L250 (35.9585, 17) -> (37.1132, 15)
    line L251 (42.8868, 15) -> (44.0415, 17)
    line L252 (44.0415, 17) -> (35.9585, 17)
    point P299 (60, 15)
    point P300 (57.1132, 15)
    point P301 (62.8868, 15)
    point P302 (64.0415, 17)
    point P303 (55.9585, 17)
    line L253 (57.1132, 15) -> (62.8868, 15)
    line L254 (55.9585, 17) -> (57.1132, 15)
    line L255 (62.8868, 15) -> (64.0415, 17)
    line L256 (64.0415, 17) -> (55.9585, 17)
    point P304 (-2.8868, 25)
    point P305 (-5.7735, 20)
    point P306 (5.7735, 20)
    point P307 (2.8868, 25)
    point P308 (-14.2265, 20)
    point P309 (-17.1132, 25)
    point P310 (-25.7735, 20)
    point P311 (-22.8868, 25)
    point P312 (14.2265, 20)
    point P313 (17.1132, 25)
    point P314 (25.7735, 20)
    point P315 (22.8868, 25)
    point P316 (7.113, 35)
    point P317 (12.8865, 35)
    point P318 (4.2262, 30)
    point P319 (7.113, 25)
    point P320 (12.8865, 25)
    point P321 (15.7733, 30)
    point P322 (-4.2262, 30)
    point P323 (-7.113, 35)
    point P324 (-7.113, 25)
    point P325 (-12.8865, 25)
    point P326 (-15.7733, 30)
    point P327 (-12.8865, 35)
    point P328 (2.8868, 65)
    point P329 (-2.8868, 65)
    point P330 (-5.7735, 60)
    point P331 (-2.8868, 55)
    point P332 (2.8868, 55)
    point P333 (5.7735, 60)
    point P334 (-2.8868, 45)
    point P335 (-5.7735, 40)
    point P336 (-2.8868, 35)
    point P337 (2.8868, 35)
    point P338 (5.7735, 40)
    point P339 (2.8868, 45)
    point P340 (0, 20)
    point P341 (7.113, 55)
    point P342 (4.2262, 50)
    point P343 (7.113, 45)
    point P344 (7, 45.1957)
    point P345 (7, 54.8043)
    point P346 (-7.113, 55)
    point P347 (-4.2262, 50)
    point P348 (-7.113, 45)
    point P349 (-7, 45.1957)
    point P350 (-7, 54.8043)
    line L257 (-5.7735, 20) -> (-2.8868, 25)
    line L258 (2.8868, 25) -> (5.7735, 20)
    line L259 (-2.8868, 25) -> (2.8868, 25)
    line L260 (-17.1132, 25) -> (-14.2265, 20)
    line L261 (-25.7735, 20) -> (-22.8868, 25)
    line L262 (-22.8868, 25) -> (-17.1132, 25)
    line L263 (17.1132, 25) -> (14.2265, 20)
    line L264 (22.8868, 25) -> (17.1132, 25)
    line L265 (25.7735, 20) -> (22.8868, 25)
    line L266 (12.8865, 35) -> (7.113, 35)
    line L267 (7.113, 35) -> (4.2262, 30)
    line L268 (4.2262, 30) -> (7.113, 25)
    line L269 (7.113, 25) -> (12.8865, 25)
    line L270 (12.8865, 25) -> (15.7733, 30)
    line L271 (15.7733, 30) -> (12.8865, 35)
    line L272 (-7.113, 35) -> (-4.2262, 30)
    line L273 (-4.2262, 30) -> (-7.113, 25)
    line L274 (-7.113, 25) -> (-12.8865, 25)
    line L275 (-12.8865, 25) -> (-15.7733, 30)
    line L276 (-15.7733, 30) -> (-12.8865, 35)
    line L277 (-12.8865, 35) -> (-7.113, 35)
    line L278 (-2.8868, 65) -> (2.8868, 65)
    line L279 (-5.7735, 60) -> (-2.8868, 65)
    line L280 (-2.8868, 55) -> (-5.7735, 60)
    line L281 (2.8868, 55) -> (-2.8868, 55)
    line L282 (5.7735, 60) -> (2.8868, 55)
    line L283 (2.8868, 65) -> (5.7735, 60)
    line L284 (-5.7735, 40) -> (-2.8868, 45)
    line L285 (-2.8868, 35) -> (-5.7735, 40)
    line L286 (2.8868, 35) -> (-2.8868, 35)
    line L287 (5.7735, 40) -> (2.8868, 35)
    line L288 (2.8868, 45) -> (5.7735, 40)
    line L289 (-2.8868, 45) -> (2.8868, 45)
    line L290 (4.2262, 50) -> (7, 54.8043)
    line L291 (7, 45.1957) -> (4.2262, 50)
    line L292 (7, 54.8043) -> (7, 45.1957)
    line L293 (-4.2262, 50) -> (-7, 54.8043)
    line L294 (-7, 45.1957) -> (-4.2262, 50)
    line L295 (-7, 54.8043) -> (-7, 45.1957)
    point P351 (-22.8868, 15)
    line L296 (-22.8868, 15) -> (-25.7735, 20)
    point P352 (-17.1132, 15)
    line L297 (-17.1132, 15) -> (-22.8868, 15)
    line L298 (-14.2265, 20) -> (-17.1132, 15)
    point P353 (-2.8868, 15)
    line L299 (-2.8868, 15) -> (-5.7735, 20)
    point P354 (2.8868, 15)
    line L300 (2.8868, 15) -> (-2.8868, 15)
    line L301 (5.7735, 20) -> (2.8868, 15)
    point P355 (17.1132, 15)
    line L302 (14.2265, 20) -> (17.1132, 15)
    point P356 (22.8868, 15)
    line L303 (17.1132, 15) -> (22.8868, 15)
    line L304 (22.8868, 15) -> (25.7735, 20)
    distance L1 L4 = 10
    distance L59 L56 = 10
    distance L63 P2 = 7.113
    coincidence: A1 P2, A1 P3, A1 P4, A1 P5, A1 P6, A1 P7, A3 P66, A3 P67, A3 P68, A3 P69, A3 P70, A3 P71, L1 L59, L231 L232, L233 P272, L233 L234
    tangency: A2 L1, A2 L2, A2 L3, A2 L4, A2 L5, A2 L6, A4 L56, A4 L57, A4 L58, A4 L59, A4 L60, A4 L61
    midpoint: P1 L1, P65 L56, L59 P73
    vertical: L7 V, L62 V, L63 V, L237 V
    symmetry: P8 P36 V, P9 P37 V, P10 P38 V, P11 P39 V, P12 P40 V, P13 P41 V, P14 P42 V, P15 P43 V, P16 P44 V, P17 P45 V, P18 P46 V, P19 P47 V, P20 P48 V, P21 P49 V, P22 P50 V, P23 P51 V, P24 P52 V, P25 P53 V, P26 P54 V, P27 P55 V, P28 P56 V, P29 P57 V, P30 P58 V, P31 P59 V, P32 P60 V, P33 P61 V, P34 P62 V, P35 P63 V, L8 L32 V, L9 L33 V, L10 L34 V, L11 L35 V, L12 L36 V, L13 L37 V, L14 L38 V, L15 L39 V, L16 L40 V, L17 L41 V, L18 L42 V, L19 L43 V, L20 L44 V, L21 L45 V, L22 L46 V, L23 L47 V, L24 L48 V, L25 L49 V, L26 L50 V, L27 L51 V, L28 L52 V, L29 L53 V, L30 L54 V, L31 L55 V, P75 P105 V, A5 A11 V, A6 A12 V, P76 P106 V, P77 P107 V, P78 P108 V, P79 P109 V, P80 P110 V, P81 P111 V, L64 L88 V, P82 P112 V, P83 P113 V, L65 L89 V, L66 L90 V, L67 L91 V, L68 L92 V, L69 L93 V, L70 L94 V, L71 L95 V, P85 P115 V, A7 A13 V, A8 A14 V, P86 P116 V, P87 P117 V, P88 P118 V, P89 P119 V, P90 P120 V, P91 P121 V, L72 L96 V, P92 P122 V, P93 P123 V, L73 L97 V, L74 L98 V, L75 L99 V, L76 L100 V, L77 L101 V, L78 L102 V, L79 L103 V, P95 P125 V, A9 A15 V, A10 A16 V, P96 P126 V, P97 P127 V, P98 P128 V, P99 P129 V, P100 P130 V, P101 P131 V, L80 L104 V, P102 P132 V, P103 P133 V, L81 L105 V, L82 L106 V, L83 L107 V, L84 L108 V, L85 L109 V, L86 L110 V, L87 L111 V, P65 P135 V, A4 A17 V, P66 P136 V, P67 P137 V, P69 P138 V, P70 P139 V, P71 P140 V, L62 L112 V, P73 P141 V, P72 P142 V, L63 L113 V, L56 L114 V, L59 L115 V, L60 L116 V, L61 L117 V, P68 P143 V, L57 L118 V, L58 L119 V, P64 P144 H, P65 P145 H, P66 P146 H, P67 P147 H, P68 P148 H, P71 P149 H, L62 L120 H, P74 P150 H, P75 P151 H, P76 P152 H, P77 P153 H, P78 P154 H, P81 P155 H, L64 L121 H, P84 P156 H, P85 P157 H, P86 P158 H, P87 P159 H, P88 P160 H, P91 P161 H, L72 L122 H, P94 P162 H, P95 P163 H, P96 P164 H, P97 P165 H, P98 P166 H, P101 P167 H, L80 L123 H, P104 P168 H, P105 P169 H, P106 P170 H, P107 P171 H, P108 P172 H, P111 P173 H, L88 L124 H, P114 P174 H, P115 P175 H, P116 P176 H, P117 P177 H, P118 P178 H, P121 P179 H, L96 L125 H, P124 P180 H, P125 P181 H, P126 P182 H, P127 P183 H, P128 P184 H, P131 P185 H, L104 L126 H, P134 P186 H, P135 P187 H, P136 P188 H, P137 P189 H, P140 P190 H, L112 L127 H, P143 P191 H, L56 L128 H, L57 L129 H, L61 L130 H, L66 L131 H, L67 L132 H, L71 L133 H, L74 L134 H, L75 L135 H, L79 L136 H, L82 L137 H, L83 L138 H, L87 L139 H, L90 L140 H, L91 L141 H, L95 L142 H, L98 L143 H, L99 L144 H, L103 L145 H, L106 L146 H, L107 L147 H, L111 L148 H, L114 L149 H, L117 L150 H, L118 L151 H, P130 P192 H, P129 P193 H, L109 L152 H, L110 L153 H, L108 L154 H, P120 P194 H, L102 L155 H, P119 P195 H, L101 L156 H, L100 L157 H, P110 P196 H, L94 L158 H, P109 P197 H, L93 L159 H, L92 L160 H, P139 P198 H, L116 L161 H, P138 P199 H, L115 L162 H, L119 L163 H, P69 P200 H, L58 L164 H, P70 P201 H, L59 L165 H, L60 L166 H, P79 P202 H, L68 L167 H, P80 P203 H, L69 L168 H, L70 L169 H, P89 P204 H, L76 L170 H, P90 P205 H, L77 L171 H, L78 L172 H, P99 P206 H, L84 L173 H, P100 P207 H, L85 L174 H, L86 L175 H, P274 P279 V, P275 P280 V, P276 P281 V, P277 P282 V, P278 P283 V, L235 L238 V, L236 L239 V, L237 L240 V, P253 P284 H, P254 P285 H, P255 P286 H, P270 P287 H, P271 P288 H, L219 L241 H, L220 L242 H, L221 L243 H, L233 L244 H, P256 P289 H, P257 P290 H, P258 P291 H, P272 P292 H, P273 P293 H, L222 L245 H, L223 L246 H, L224 L247 H, L234 L248 H, P260 P294 H, P261 P295 H, P262 P296 H, P268 P297 H, P269 P298 H, L225 L249 H, L226 L250 H, L227 L251 H, L232 L252 H, P263 P299 H, P264 P300 H, P265 P301 H, P266 P302 H, P267 P303 H, L228 L253 H, L229 L254 H, L230 L255 H, L231 L256 H, P208 P304 H, P209 P305 H, P212 P306 H, P213 P307 H, P214 P308 H, P215 P309 H, P218 P310 H, P219 P311 H, P221 P312 H, P222 P313 H, P223 P314 H, P225 P315 H, P226 P316 H, P227 P317 H, P228 P318 H, P229 P319 H, P230 P320 H, P231 P321 H, P232 P322 H, P233 P323 H, P234 P324 H, P235 P325 H, P236 P326 H, P237 P327 H, P238 P328 H, P239 P329 H, P240 P330 H, P241 P331 H, P242 P332 H, P243 P333 H, P244 P334 H, P245 P335 H, P246 P336 H, P247 P337 H, P248 P338 H, P249 P339 H, P250 P340 H, P274 P341 H, P275 P342 H, P276 P343 H, P277 P344 H, P278 P345 H, P279 P346 H, P280 P347 H, P281 P348 H, P282 P349 H, P283 P350 H, L176 L257 H, L180 L258 H, L181 L259 H, L182 L260 H, L186 L261 H, L187 L262 H, L189 L263 H, L192 L264 H, L193 L265 H, L194 L266 H, L195 L267 H, L196 L268 H, L197 L269 H, L198 L270 H, L199 L271 H, L200 L272 H, L201 L273 H, L202 L274 H, L203 L275 H, L204 L276 H, L205 L277 H, L206 L278 H, L207 L279 H, L208 L280 H, L209 L281 H, L210 L282 H, L211 L283 H, L212 L284 H, L213 L285 H, L214 L286 H, L215 L287 H, L216 L288 H, L217 L289 H, L235 L290 H, L236 L291 H, L237 L292 H, L238 L293 H, L239 L294 H, L240 L295 H, P217 P351 H, L185 L296 H, P216 P352 H, L184 L297 H, L183 L298 H, P210 P353 H, L177 L299 H, P211 P354 H, L178 L300 H, L179 L301 H, P220 P355 H, L188 L302 H, P224 P356 H, L191 L303 H, L190 L304 H
    horizontal: L231 H, L232 H, L233 H, L234 H
  Pocket2: profile Sketch4, direction (0, 1, 0), through (limit type 6)
  Fillet1: radius 30, on edge [face of Pad1 from Sketch1.L22 | face of Pad1 from Sketch1.L21]; edge [face of Pad1 from Sketch1.L11 | face of Pad1 from Sketch1.L9]; edge [face of Pad1 from Sketch1.L4 | face of Pad1 from Sketch1.L6]; edge [face of Pad1 from Sketch1.L24 | face of Pad1 from Sketch1.L23]
  Chamfer1: length 5, angle 75, on edge [face of Pad2 from Sketch2.L2 | end face of Pad2]; edge [face of Pad2 from Sketch2.L10 | end face of Pad2]; edge [face of Pad2 from Sketch2.L14 | end face of Pad2]; edge [face of Pad2 from Sketch2.L6 | end face of Pad2]
  Sketch5 on face of Pad2, origin (0, 0, 45), H (1, 0, 0), V (0, 1, 0)
    point P1 (115.5, 5)
    line L1 (115.5, 5) -> (116.5, 5)
    line L2 (116.5, 5) -> (116.5, -18.258)
    line L3 (115.5, -10) -> (115.5, 5)
    point P2 (116.5, 5)
    reference projected line E1 (91.5, 5) -> (116.5, 5) from edge [face of Pad2 | end face of Pad1]
    reference projected line E2 (116.5, 0) -> (116.5, 5) from edge [face of Pad2 | face of Pad2]
    reference projected arc E3 centre (107, -10) radius 7.5 from (99.567, -11) to (99.567, -9) ccw from edge [face of Pad2 | face of Pocket1 from Sketch3.A2]
    point P3 (107, -18.5)
    line L4 (116.5, -18.258) -> (116.5, -20)
    line L5 (116.5, -20) -> (110.1603, -20)
    point P4 (116.5, -18.258)
    point P5 (116.5, -20)
    point P6 (110.1603, -20)
    point P7 (116.5, -18.258)
    line L6 (116.5, -18.258) -> (116.5, -18.258)
    reference projected line E4 (116.5, -20) -> (91.5, -20) from edge [face of Pad2 | end face of Pad2]
    arc A1 centre (107, -10) radius 8.5 from (107.4722, -18.4869) to (115.5, -10) ccw
    point P9 (115.5, -10)
    point P10 (107, -18.5)
    point P11 (115.5, -10)
    point P12 (91.5, -15)
    reference projected line E5 (110.1603, -20) -> (91.5, -15) from edge [face of Pad2 | face of Chamfer1]
    line L7 (110.1603, -20) -> (107, -19.1532)
    point P13 (107, -19.1532)
    line L8 (107, -19.1532) -> (107, -18.9861)
    arc A2 centre (107.5, -18.9861) radius 0.5 from (107.4722, -18.4869) to (107, -18.9861) ccw
    point P14 (107.4722, -18.4869)
    point P15 (107, -18.9861)
    point P17 (-115.5, 5)
    point P18 (-116.5, 5)
    point P19 (-107, -18.5)
    point P20 (-116.5, -18.258)
    point P21 (-116.5, -20)
    point P22 (-110.1603, -20)
    point P23 (-116.5, -18.258)
    point P25 (-115.5, -10)
    point P26 (-107, -18.5)
    point P27 (-115.5, -10)
    point P28 (-91.5, -15)
    point P29 (-107, -19.1532)
    point P30 (-107.4722, -18.4869)
    point P31 (-107, -18.9861)
    line L9 (-115.5, 5) -> (-116.5, 5)
    line L10 (-116.5, 5) -> (-116.5, -18.258)
    line L11 (-115.5, -10) -> (-115.5, 5)
    line L12 (-116.5, -18.258) -> (-116.5, -20)
    line L13 (-116.5, -20) -> (-110.1603, -20)
    arc A3 centre (-107, -10) radius 8.5 from (-107.4722, -18.4869) to (-115.5, -10) cw
    line L14 (-110.1603, -20) -> (-107, -19.1532)
    line L15 (-107, -19.1532) -> (-107, -18.9861)
    arc A4 centre (-107.5, -18.9861) radius 0.5 from (-107.4722, -18.4869) to (-107, -18.9861) cw
    distance E3 L3 = 1
    distance A1 E3 = 1
    distance L8 L4 = 9.5
    radius A2 = 0.5
    horizontal: L1 H, L5 H, L6 H
    vertical: L2 V, L3 V, L4 V, L8 V
    coincidence: E1 L1, E2 L2, E2 L4, L5 E4, A1 P9, L3 P11, P12 E5, P3 P10, E5 L7, A1 P10, L8 P3
    concentricity: A1 E3
    tangency: A2 L8, A2 A1
    symmetry: P1 P17 V, P2 P18 V, P3 P19 V, P4 P20 V, P5 P21 V, P6 P22 V, P7 P23 V, P9 P25 V, P10 P26 V, P11 P27 V, P12 P28 V, P13 P29 V, P14 P30 V, P15 P31 V, L1 L9 V, L2 L10 V, L3 L11 V, L4 L12 V, L5 L13 V, A1 A3 V, L7 L14 V, L8 L15 V, A2 A4 V
  Pocket3: profile Sketch5, direction (0, 0, -1), through (limit type 3)
  Sketch6 on face of Pad1, origin (0, 0, 0), H (1, 0, 0), V (0, 0, 1)
    point P1 (-7.8455, 25)
    construction line L1 (-7.8455, 25) -> (7.8455, 25)
    point P2 (7.8455, 25)
    point P3 (7.8455, 25)
    construction line L2 (7.8455, 25) -> (7.8455, -25)
    construction line L3 (-7.8455, 25) -> (-7.8455, -25)
    construction line L4 (-7.8455, -25) -> (7.8455, -25)
    circle A1 centre (9.5955, 0) radius 1.75
    point P6 (9.5955, 0)
    circle A2 centre (-9.5955, 0) radius 1.75
    length L1 = 15.691
    distance P1 V = 7.8455
    length L2 = 50
    distance H L1 = 25
    radius A1 = 1.75
    horizontal: L1 H, L4 H
    coincidence: P3 L1, P2 P3, P6 H
    vertical: L2 V, L3 V
    tangency: A1 L2
    symmetry: A1 A2 V
  Pocket4: profile Sketch6, direction (0, 1, 0), through (limit type 6)
  Sketch7 on end face of Pad1, origin (0, 5, 0), H (-1, 0, 0), V (0, 0, 1)
    point P2 (-9.5955, 2.7)
    construction circle A1 centre (-9.5955, 0) radius 3.1177
    construction circle A2 centre (-9.5955, 0) radius 2.7
    point P3 (-8.0367, 2.7)
    point P4 (-11.1543, 2.7)
    point P5 (-12.7132, 0)
    point P6 (-11.1543, -2.7)
    point P7 (-8.0367, -2.7)
    point P8 (-6.4778, 0)
    line L1 (-8.0367, 2.7) -> (-11.1543, 2.7)
    line L2 (-11.1543, 2.7) -> (-12.7132, 0)
    line L3 (-12.7132, 0) -> (-11.1543, -2.7)
    line L4 (-11.1543, -2.7) -> (-8.0367, -2.7)
    line L5 (-8.0367, -2.7) -> (-6.4778, 0)
    line L6 (-6.4778, 0) -> (-8.0367, 2.7)
    construction line L7 (-9.5955, 0) -> (-9.5955, 2.7)
    reference projected circle E1 centre (-9.5955, 0) radius 1.75 from edge [end face of Pad1 | face of Pocket4 from Sketch6.A1]
    point P10 (9.5955, 2.7)
    construction circle A3 centre (9.5955, 0) radius 3.1177
    construction circle A4 centre (9.5955, 0) radius 2.7
    point P11 (8.0367, 2.7)
    point P12 (11.1543, 2.7)
    point P13 (12.7132, 0)
    point P14 (11.1543, -2.7)
    point P15 (8.0367, -2.7)
    point P16 (6.4778, 0)
    construction line L8 (9.5955, 0) -> (9.5955, 2.7)
    line L9 (8.0367, 2.7) -> (11.1543, 2.7)
    line L10 (11.1543, 2.7) -> (12.7132, 0)
    line L11 (12.7132, 0) -> (11.1543, -2.7)
    line L12 (11.1543, -2.7) -> (8.0367, -2.7)
    line L13 (8.0367, -2.7) -> (6.4778, 0)
    line L14 (6.4778, 0) -> (8.0367, 2.7)
    distance L1 L4 = 5.4
    coincidence: A1 P3, A1 P4, A1 P5, A1 P6, A1 P7, A1 P8
    tangency: A2 L1, A2 L2, A2 L3, A2 L4, A2 L5, A2 L6
    midpoint: P2 L1
    vertical: L7 V
    concentricity: A2 E1
    symmetry: P2 P10 V, A1 A3 V, A2 A4 V, P3 P11 V, P4 P12 V, P5 P13 V, P6 P14 V, P7 P15 V, P8 P16 V, L7 L8 V, L1 L9 V, L2 L10 V, L3 L11 V, L4 L12 V, L5 L13 V, L6 L14 V
  Pocket5: profile Sketch7, direction (0, -1, 0), length 3
  DatumCurve1
  Sketch8 on start face of Pad1, origin (0, 0, 0), H (1, 0, 0), V (0, 0, 1)
    circle A1 centre (95.5468, -37.5) radius 1.75
    reference projected circle E1 centre (95.5468, -37.5) radius 1.5 from edge of DatumCurve1
    circle A2 centre (-95.5468, -37.5) radius 1.75
    circle A3 centre (95.5468, 37.5) radius 1.75
    circle A4 centre (-95.5468, 37.5) radius 1.75
    radius A1 = 1.75
    concentricity: A1 E1
    symmetry: A1 A2 V, A1 A3 H, A2 A4 H
  Pocket6: profile Sketch8, direction (0, -1, 0), through (limit type 3), opposite side through (limit type 3)
  DatumCurve2
  Sketch9 on start face of Pad1, origin (0, 0, 0), H (1, 0, 0), V (0, 0, 1)
    point P2 (95.5468, -34.75)
    construction circle A1 centre (95.5468, -37.5) radius 3.1754
    construction arc A2 centre (95.5468, -37.5) radius 2.75 from (93.1652, -38.875) to (93.1652, -36.125) ccw
    point P3 (97.1345, -34.75)
    point P4 (93.9591, -34.75)
    point P5 (93.9591, -40.25)
    point P6 (97.1345, -40.25)
    point P7 (98.7222, -37.5)
    line L1 (97.1345, -34.75) -> (93.9591, -34.75)
    line L2 (93.9591, -40.25) -> (97.1345, -40.25)
    line L3 (97.1345, -40.25) -> (98.7222, -37.5)
    line L4 (98.7222, -37.5) -> (97.1345, -34.75)
    construction line L5 (95.5468, -37.5) -> (95.5468, -34.75)
    reference projected circle E1 centre (95.5468, -37.5) radius 1.5 from edge of DatumCurve2
    line L6 (93.9591, -34.75) -> (91.5, -34.75)
    point P8 (91.5, -34.75)
    line L7 (91.5, -34.75) -> (91.5, -40.25)
    point P9 (91.5, -40.25)
    line L8 (91.5, -40.25) -> (93.9591, -40.25)
    point P10 (93.9591, -40.25)
    reference projected line E2 (91.5, -30) -> (91.5, -45) from edge [face of Pad2 from Sketch2.L14 | face of Chamfer1]
    point P11 (93.1652, -36.125)
    point P12 (93.1652, -38.875)
    point P14 (95.5468, 34.75)
    construction circle A3 centre (95.5468, 37.5) radius 3.1754
    point P15 (93.1652, 36.125)
    point P16 (93.1652, 38.875)
    construction arc A4 centre (95.5468, 37.5) radius 2.75 from (93.1652, 38.875) to (93.1652, 36.125) cw
    point P17 (97.1345, 34.75)
    point P18 (93.9591, 34.75)
    point P19 (93.9591, 40.25)
    point P20 (97.1345, 40.25)
    point P21 (98.7222, 37.5)
    construction line L9 (95.5468, 37.5) -> (95.5468, 34.75)
    point P22 (91.5, 34.75)
    point P23 (91.5, 40.25)
    point P24 (93.9591, 40.25)
    line L10 (97.1345, 34.75) -> (93.9591, 34.75)
    line L11 (93.9591, 40.25) -> (97.1345, 40.25)
    line L12 (97.1345, 40.25) -> (98.7222, 37.5)
    line L13 (98.7222, 37.5) -> (97.1345, 34.75)
    line L14 (93.9591, 34.75) -> (91.5, 34.75)
    line L15 (91.5, 34.75) -> (91.5, 40.25)
    line L16 (91.5, 40.25) -> (93.9591, 40.25)
    point P26 (-95.5468, -34.75)
    construction circle A5 centre (-95.5468, -37.5) radius 3.1754
    point P27 (-93.1652, -36.125)
    point P28 (-93.1652, -38.875)
    construction arc A6 centre (-95.5468, -37.5) radius 2.75 from (-93.1652, -38.875) to (-93.1652, -36.125) cw
    point P29 (-97.1345, -34.75)
    point P30 (-93.9591, -34.75)
    point P31 (-93.9591, -40.25)
    point P32 (-97.1345, -40.25)
    point P33 (-98.7222, -37.5)
    construction line L17 (-95.5468, -37.5) -> (-95.5468, -34.75)
    point P34 (-91.5, -34.75)
    point P35 (-91.5, -40.25)
    point P36 (-93.9591, -40.25)
    point P38 (-95.5468, 34.75)
    construction circle A7 centre (-95.5468, 37.5) radius 3.1754
    point P39 (-93.1652, 36.125)
    point P40 (-93.1652, 38.875)
    construction arc A8 centre (-95.5468, 37.5) radius 2.75 from (-93.1652, 38.875) to (-93.1652, 36.125) ccw
    point P41 (-97.1345, 34.75)
    point P42 (-93.9591, 34.75)
    point P43 (-93.9591, 40.25)
    point P44 (-97.1345, 40.25)
    point P45 (-98.7222, 37.5)
    construction line L18 (-95.5468, 37.5) -> (-95.5468, 34.75)
    point P46 (-91.5, 34.75)
    point P47 (-91.5, 40.25)
    point P48 (-93.9591, 40.25)
    line L19 (-97.1345, -34.75) -> (-93.9591, -34.75)
    line L20 (-93.9591, -40.25) -> (-97.1345, -40.25)
    line L21 (-97.1345, -40.25) -> (-98.7222, -37.5)
    line L22 (-98.7222, -37.5) -> (-97.1345, -34.75)
    line L23 (-93.9591, -34.75) -> (-91.5, -34.75)
    line L24 (-91.5, -34.75) -> (-91.5, -40.25)
    line L25 (-91.5, -40.25) -> (-93.9591, -40.25)
    line L26 (-97.1345, 34.75) -> (-93.9591, 34.75)
    line L27 (-93.9591, 40.25) -> (-97.1345, 40.25)
    line L28 (-97.1345, 40.25) -> (-98.7222, 37.5)
    line L29 (-98.7222, 37.5) -> (-97.1345, 34.75)
    line L30 (-93.9591, 34.75) -> (-91.5, 34.75)
    line L31 (-91.5, 34.75) -> (-91.5, 40.25)
    line L32 (-91.5, 40.25) -> (-93.9591, 40.25)
    distance L1 L2 = 5.5
    coincidence: A1 P3, A1 P4, A1 P5, A1 P6, A1 P7, P9 L2, P10 A1, L7 E2, P5 P10, P19 P24, P31 P36, P43 P48
    tangency: A2 L1, A2 L2, A2 L3, A2 L4, L6 A2, L8 A2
